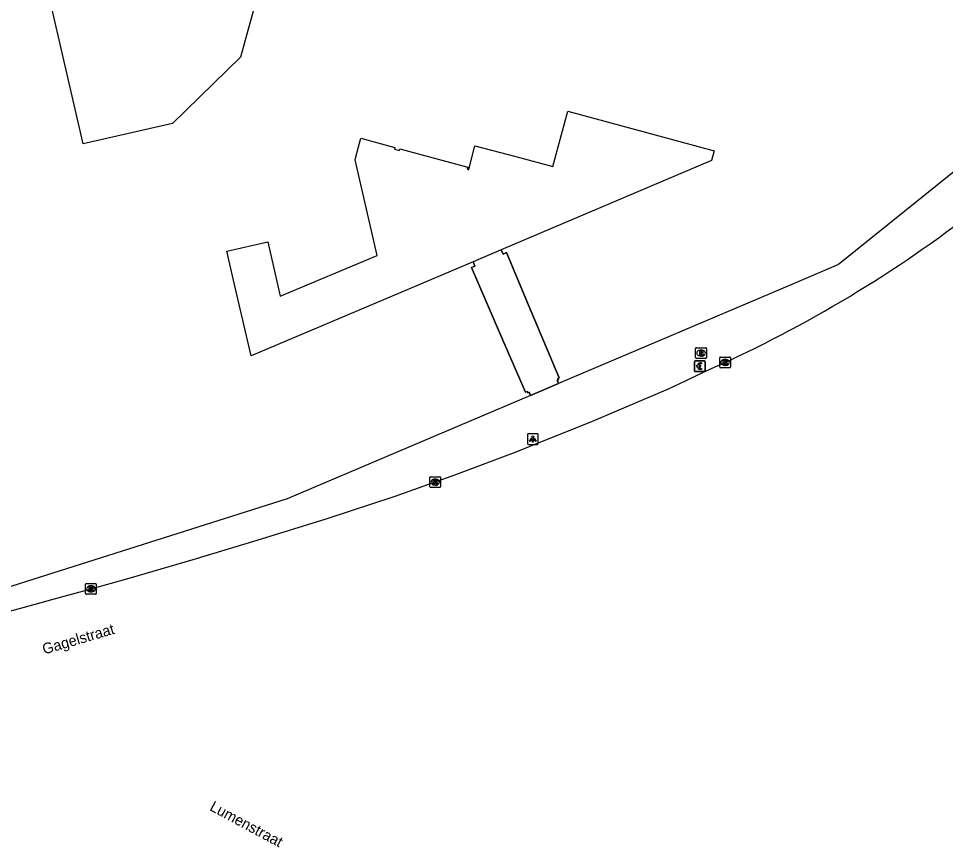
# Model space of a CAD drawing. Extents: x 160676 to 161153, y 383244 to 383713.
# Drawn here: x 160742.2 to 160828.6, y 383455.7 to 383533 of the extents above; entities that cross this region are included whole.
import ezdxf

# ---------------------------------------------------------------- set-up
doc = ezdxf.new("R2010")
doc.units = 0
for name, color, linetype in [('IMGEO_Betaalautomaat', 7, 'Continuous'), ('IMGEO_Brandkraan', 7, 'Continuous'), ('IMGEO_Kolk', 7, 'Continuous'), ('IMGEO_Lichtpunt', 7, 'Continuous'), ('IMGEO_Openbare_ruimte_label', 7, 'Continuous'), ('IMGEO_Pand', 7, 'Continuous'), ('IMGEO_Pand_overbouw', 7, 'Continuous'), ('IMGEO_Voetpad_open', 7, 'Continuous')]:
    doc.layers.add(name, color=color, linetype=linetype)

msp = doc.modelspace()

# ---------------------------------------------------------------- linework, layer by layer
at = {"layer": 'IMGEO_Betaalautomaat'}
for p, q in [((160805.261, 383501.089), (160806.102, 383501.089)), ((160806.102, 383501.089), (160805.261, 383501.089)), ((160805.186, 383500.165), (160805.186, 383501.006)), ((160805.186, 383501.006), (160805.186, 383500.165)), ((160805.469, 383500.553), (160805.469, 383500.621)), ((160805.59, 383500.621), (160805.59, 383500.553)), ((160805.848, 383500.894), (160805.831, 383500.794)), ((160805.835, 383500.388), (160805.857, 383500.301)), ((160806.185, 383501.015), (160806.185, 383500.174)), ((160806.185, 383500.174), (160806.185, 383501.015)), ((160806.111, 383500.09), (160805.27, 383500.09)), ((160805.27, 383500.09), (160806.111, 383500.09))]:
    msp.add_line(p, q, dxfattribs=at)
for points in [[(160805.469, 383500.621), (160805.4, 383500.621), (160805.4, 383500.69), (160805.479, 383500.69)], [(160805.474, 383500.484), (160805.4, 383500.484), (160805.4, 383500.553), (160805.469, 383500.553)], [(160805.601, 383500.69), (160805.748, 383500.69), (160805.748, 383500.621), (160805.59, 383500.621)], [(160805.59, 383500.553), (160805.748, 383500.553), (160805.748, 383500.484), (160805.604, 383500.484)]]:
    msp.add_lwpolyline(points, dxfattribs=at)
for centre, radius, start, end in [((160805.264, 383501.012), 0.0779, 92.4484, 184.28452), ((160805.264, 383501.012), 0.0779, 92.4484, 184.28452), ((160806.108, 383501.012), 0.0779, 2.4484, 94.28452), ((160806.108, 383501.012), 0.0779, 2.4484, 94.28452), ((160805.264, 383500.168), 0.0779, 182.4484, 274.28452), ((160805.264, 383500.168), 0.0779, 182.4484, 274.28452), ((160805.735, 383500.539), 0.267, 191.80956, 297.03891), ((160805.762, 383500.614), 0.293, 73.01398, 165.01395), ((160805.768, 383500.627), 0.179, 69.32359, 159.56827), ((160805.768, 383500.554), 0.179, 202.76249, 291.86925), ((160806.108, 383500.168), 0.0779, 272.4484, 4.28452), ((160806.108, 383500.168), 0.0779, 272.4484, 4.28452)]:
    msp.add_arc(centre, radius, start, end, dxfattribs=at)
at = {"layer": 'IMGEO_Brandkraan'}
for p, q in [((160805.294, 383501.387), (160805.294, 383502.239)), ((160805.369, 383502.313), (160806.221, 383502.313)), ((160805.782, 383502.093), (160805.807, 383502.093)), ((160806.295, 383502.239), (160806.295, 383501.387)), ((160806.221, 383501.313), (160805.369, 383501.313)), ((160805.805, 383501.533), (160805.78, 383501.533))]:
    msp.add_line(p, q, dxfattribs=at)
for points in [[(160805.294, 383501.387), (160805.294, 383502.239)], [(160805.369, 383502.313), (160806.221, 383502.313)], [(160805.642, 383502.013), (160805.642, 383501.613), (160805.855, 383501.613)], [(160805.873, 383502.013), (160805.642, 383502.013)], [(160805.821, 383501.932), (160805.767, 383501.932), (160805.767, 383501.856)], [(160806.295, 383502.239), (160806.295, 383501.387)], [(160806.221, 383501.313), (160805.369, 383501.313)], [(160805.767, 383501.856), (160805.82, 383501.856)], [(160805.829, 383501.78), (160805.767, 383501.78), (160805.767, 383501.699)], [(160805.767, 383501.699), (160805.829, 383501.699)]]:
    msp.add_lwpolyline(points, dxfattribs=at)
for centre, radius, start, end in [((160805.371, 383502.237), 0.0765, 91.55205, 178.44795), ((160805.371, 383502.237), 0.0765, 91.55205, 178.44795), ((160805.822, 383501.894), 0.0379, 267.82845, 90.93552), ((160805.877, 383501.868), 0.145, 59.4692, 91.53667), ((160805.902, 383501.915), 0.0922, 285.51372, 58.15012), ((160806.219, 383502.237), 0.0765, 1.55205, 88.44795), ((160806.219, 383502.237), 0.0765, 1.55205, 88.44795), ((160805.371, 383501.389), 0.0765, 181.55205, 268.44795), ((160805.371, 383501.389), 0.0765, 181.55205, 268.44795), ((160805.83, 383501.739), 0.0404, 269.87594, 90.50774), ((160805.861, 383501.864), 0.251, 268.66757, 293.53466), ((160805.907, 383501.723), 0.105, 301.31148, 78.98903), ((160806.219, 383501.389), 0.0765, 271.55205, 358.44795), ((160806.219, 383501.389), 0.0765, 271.55205, 358.44795)]:
    msp.add_arc(centre, radius, start, end, dxfattribs=at)
for centre, major_axis, ratio, start_param, end_param in [((160805.781, 383501.813), (-0.387, 0.002), 0.722429, 4.712389, 7.853982), ((160805.806, 383501.813), (-0.39, 0.002), 0.717154, 1.570796, 4.712389)]:
    msp.add_ellipse(centre, major_axis=major_axis, ratio=ratio, start_param=start_param, end_param=end_param, dxfattribs=at)
at = {"layer": 'IMGEO_Kolk'}
for p, q in [((160807.536, 383500.516), (160807.536, 383501.368)), ((160807.611, 383501.442), (160808.463, 383501.442)), ((160808.024, 383501.222), (160808.049, 383501.222)), ((160808.537, 383501.368), (160808.537, 383500.516)), ((160808.463, 383500.442), (160807.611, 383500.442)), ((160808.047, 383500.662), (160808.022, 383500.662)), ((160780.512, 383489.361), (160780.512, 383490.213)), ((160780.587, 383490.287), (160781.439, 383490.287)), ((160781, 383490.067), (160781.025, 383490.067)), ((160781.513, 383490.213), (160781.513, 383489.361)), ((160781.439, 383489.287), (160780.587, 383489.287)), ((160781.023, 383489.507), (160780.998, 383489.507)), ((160748.501, 383480.336), (160749.353, 383480.336)), ((160748.426, 383479.41), (160748.426, 383480.262)), ((160748.937, 383479.556), (160748.912, 383479.556)), ((160748.914, 383480.116), (160748.939, 383480.116)), ((160749.427, 383480.262), (160749.427, 383479.41)), ((160749.353, 383479.336), (160748.501, 383479.336))]:
    msp.add_line(p, q, dxfattribs=at)
for points in [[(160807.536, 383500.516), (160807.536, 383501.368)], [(160807.611, 383501.442), (160808.463, 383501.442)], [(160807.857, 383501.142), (160807.98, 383501.142), (160807.98, 383500.991), (160808.11, 383501.142), (160808.274, 383501.142), (160808.128, 383500.991), (160808.281, 383500.742), (160808.129, 383500.742), (160808.044, 383500.906), (160807.98, 383500.839), (160807.98, 383500.742), (160807.857, 383500.742), (160807.857, 383501.142)], [(160808.537, 383501.368), (160808.537, 383500.516)], [(160808.463, 383500.442), (160807.611, 383500.442)], [(160780.512, 383489.361), (160780.512, 383490.213)], [(160780.587, 383490.287), (160781.439, 383490.287)], [(160780.833, 383489.987), (160780.956, 383489.987), (160780.956, 383489.836), (160781.086, 383489.987), (160781.25, 383489.987), (160781.104, 383489.836), (160781.257, 383489.587), (160781.105, 383489.587), (160781.02, 383489.751), (160780.956, 383489.684), (160780.956, 383489.587), (160780.833, 383489.587), (160780.833, 383489.987)], [(160781.513, 383490.213), (160781.513, 383489.361)], [(160781.439, 383489.287), (160780.587, 383489.287)], [(160748.501, 383480.336), (160749.353, 383480.336)], [(160748.426, 383479.41), (160748.426, 383480.262)], [(160748.747, 383480.036), (160748.87, 383480.036), (160748.87, 383479.885), (160749, 383480.036), (160749.164, 383480.036), (160749.018, 383479.885), (160749.171, 383479.636), (160749.019, 383479.636), (160748.934, 383479.8), (160748.87, 383479.733), (160748.87, 383479.636), (160748.747, 383479.636), (160748.747, 383480.036)], [(160749.427, 383480.262), (160749.427, 383479.41)], [(160749.353, 383479.336), (160748.501, 383479.336)]]:
    msp.add_lwpolyline(points, dxfattribs=at)
for centre, start, end in [((160807.613, 383501.366), 91.55205, 178.44795), ((160807.613, 383501.366), 91.55205, 178.44795), ((160808.461, 383501.366), 1.55205, 88.44795), ((160808.461, 383501.366), 1.55205, 88.44795), ((160807.613, 383500.518), 181.55205, 268.44795), ((160807.613, 383500.518), 181.55205, 268.44795), ((160808.461, 383500.518), 271.55205, 358.44795), ((160808.461, 383500.518), 271.55205, 358.44795), ((160780.589, 383490.211), 91.55205, 178.44795), ((160780.589, 383490.211), 91.55205, 178.44795), ((160781.437, 383490.211), 1.55205, 88.44795), ((160781.437, 383490.211), 1.55205, 88.44795), ((160780.589, 383489.363), 181.55205, 268.44795), ((160780.589, 383489.363), 181.55205, 268.44795), ((160781.437, 383489.363), 271.55205, 358.44795), ((160781.437, 383489.363), 271.55205, 358.44795), ((160748.503, 383480.26), 91.55205, 178.44795), ((160748.503, 383480.26), 91.55205, 178.44795), ((160749.351, 383480.26), 1.55205, 88.44795), ((160749.351, 383480.26), 1.55205, 88.44795), ((160748.503, 383479.412), 181.55205, 268.44795), ((160748.503, 383479.412), 181.55205, 268.44795), ((160749.351, 383479.412), 271.55205, 358.44795), ((160749.351, 383479.412), 271.55205, 358.44795)]:
    msp.add_arc(centre, 0.0765, start, end, dxfattribs=at)
for centre, major_axis, ratio, start_param, end_param in [((160808.023, 383500.942), (-0.387, 0.002), 0.722429, 4.712389, 7.853982), ((160808.048, 383500.942), (-0.39, 0.002), 0.717154, 1.570796, 4.712389), ((160780.999, 383489.787), (-0.387, 0.002), 0.722429, 4.712389, 7.853982), ((160781.024, 383489.787), (-0.39, 0.002), 0.717154, 1.570796, 4.712389), ((160748.913, 383479.836), (-0.387, 0.002), 0.722429, 4.712389, 7.853982), ((160748.938, 383479.836), (-0.39, 0.002), 0.717154, 1.570796, 4.712389)]:
    msp.add_ellipse(centre, major_axis=major_axis, ratio=ratio, start_param=start_param, end_param=end_param, dxfattribs=at)
at = {"layer": 'IMGEO_Lichtpunt'}
for p, q in [((160789.612, 383494.205), (160789.612, 383493.398)), ((160789.612, 383494.205), (160789.612, 383493.398)), ((160790.514, 383494.3), (160789.706, 383494.3)), ((160790.514, 383494.3), (160789.706, 383494.3)), ((160790.608, 383493.398), (160790.608, 383494.205)), ((160790.608, 383493.398), (160790.608, 383494.205)), ((160789.706, 383493.304), (160790.514, 383493.304)), ((160789.706, 383493.304), (160790.514, 383493.304))]:
    msp.add_line(p, q, dxfattribs=at)
for points in [[(160789.986, 383493.869), (160790.025, 383493.841), (160789.837, 383493.579), (160789.799, 383493.606), (160789.986, 383493.869)], [(160790.088, 383493.821), (160790.135, 383493.821), (160790.135, 383493.499), (160790.088, 383493.499), (160790.088, 383493.821)], [(160790.198, 383493.841), (160790.236, 383493.868), (160790.423, 383493.606), (160790.384, 383493.578), (160790.198, 383493.841)]]:
    msp.add_lwpolyline(points, dxfattribs=at)
msp.add_circle((160790.111, 383494.003), 0.0994, dxfattribs=at)
for centre, start, end in [((160789.706, 383494.205), 90, 180), ((160789.706, 383494.205), 90, 180), ((160790.514, 383494.205), 0, 90), ((160790.514, 383494.205), 0, 90), ((160789.706, 383493.398), 180, 270), ((160789.706, 383493.398), 180, 270), ((160790.514, 383493.398), 270, 0), ((160790.514, 383493.398), 270, 360)]:
    msp.add_arc(centre, 0.0946, start, end, dxfattribs=at)
at = {"layer": 'IMGEO_Pand'}
for points in [[(160762.882, 383529.378), (160756.534, 383523.204), (160748.196, 383521.306), (160743.335, 383542.457), (160744.154, 383543.281), (160754.382, 383540.56), (160765.12, 383537.659), (160762.882, 383529.378)], [(160789.904, 383497.87), (160789.775, 383498.174), (160789.646, 383498.119), (160789.599, 383498.23), (160789.439, 383498.158), (160787.332, 383503.027), (160784.409, 383509.785), (160784.724, 383509.918), (160784.556, 383510.314), (160777.813, 383507.449), (160763.853, 383501.549), (160762.41, 383507.791), (160761.603, 383511.315), (160765.407, 383512.17), (160766.579, 383507.103), (160775.608, 383510.92), (160773.542, 383519.822), (160773.584, 383519.977), (160773.87, 383521.033), (160774.085, 383521.825), (160777.259, 383520.964), (160777.217, 383520.799), (160777.664, 383520.687), (160777.707, 383520.85), (160784.058, 383519.149), (160784.002, 383518.957), (160784.091, 383518.931), (160784.138, 383518.917), (160784.721, 383521.14), (160788.523, 383520.123), (160791.985, 383519.194), (160793.365, 383524.343), (160807.01, 383520.658), (160806.762, 383519.761), (160787.176, 383511.439), (160787.344, 383511.043), (160787.65, 383511.173), (160789.726, 383506.268), (160792.586, 383499.509), (160792.443, 383499.445), (160792.502, 383499.329), (160792.373, 383499.274), (160792.502, 383498.971)], [(160835.583, 383523.701), (160818.62, 383510.07), (160814.473, 383508.308), (160792.502, 383498.971)], [(160789.904, 383497.87), (160767.23, 383488.234), (160738.303, 383479.05), (160737.884, 383480.656)]]:
    msp.add_lwpolyline(points, dxfattribs=at)
at = {"layer": 'IMGEO_Pand_overbouw'}
msp.add_lwpolyline([(160792.502, 383498.971), (160792.373, 383499.274), (160792.502, 383499.329), (160792.443, 383499.445), (160792.586, 383499.509), (160789.726, 383506.268), (160787.65, 383511.173), (160787.344, 383511.043), (160787.176, 383511.439), (160784.556, 383510.314), (160784.724, 383509.918), (160784.409, 383509.785), (160787.332, 383503.027), (160789.439, 383498.158), (160789.599, 383498.23), (160789.646, 383498.119), (160789.775, 383498.174), (160789.904, 383497.87)], close=True, dxfattribs=at)
at = {"layer": 'IMGEO_Voetpad_open'}
for points in [[(160737.233, 383476.662), (160742.593, 383478.11), (160745.398, 383478.868), (160748.941, 383479.839), (160752.477, 383480.836), (160758.455, 383482.574), (160764.417, 383484.369), (160770.863, 383486.368), (160777.275, 383488.471), (160782.936, 383490.488), (160788.554, 383492.621), (160789.861, 383493.144), (160795.666, 383495.465), (160795.689, 383495.474), (160802.758, 383498.486), (160804.362, 383499.229), (160805.953, 383500)], [(160792.502, 383498.971), (160789.904, 383497.87)]]:
    msp.add_lwpolyline(points, dxfattribs=at)
msp.add_arc((160757.151, 383610.954), 121.212, 293.7416, 307.47749, dxfattribs=at)

# ---------------------------------------------------------------- texts
at = {"layer": 'IMGEO_Openbare_ruimte_label'}
for s, rotation, p in [('Gagelstraat', 16.37015, (160744.568, 383473.717)), ('Lumenstraat', 331.7691, (160759.917, 383459.246))]:
    msp.add_text(s, height=1, rotation=rotation, dxfattribs=at).set_placement(p)

doc.saveas('drawing.dxf')
